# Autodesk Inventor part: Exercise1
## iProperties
Shininess: 64.0
Length Units: 11269
Angle Units: 11279
Time Units: 11290
Mass Units: 11283
Length Display Precision: 3
Angle Display Precision: 2
Compacted: True
Created: 2002-02
Part Number: Exercise1
Document SubType Name: Modeling
Density: 0.0
Volumn: 0.0
Area: 0.0
PropertySet Name: Model Information
Control State: 0
Master: False
Checked Out: False
